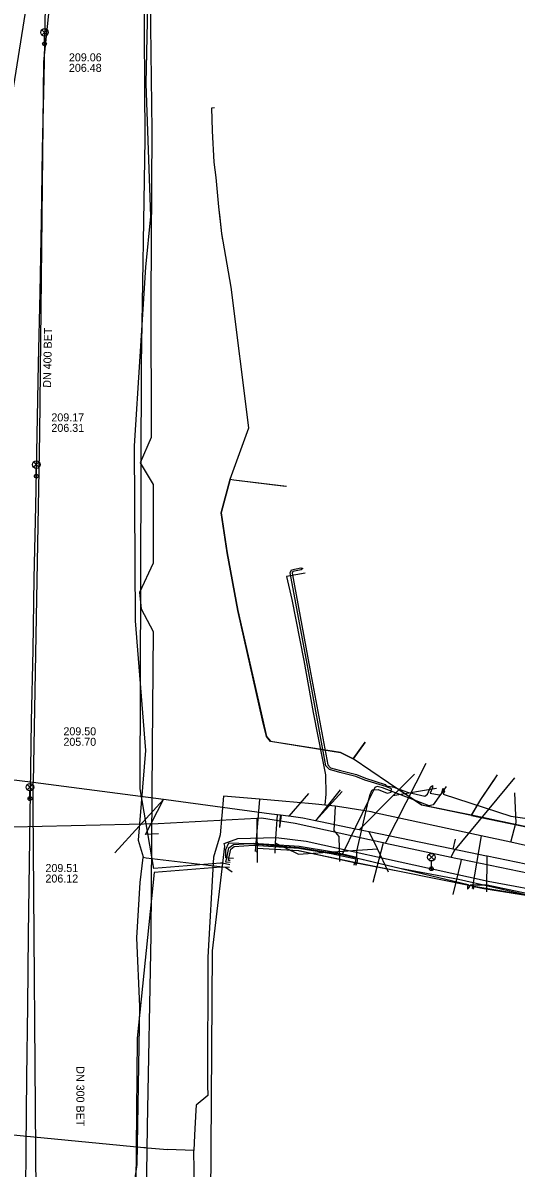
# Model space of a CAD drawing. Extents: x -596228 to -595156, y -1161235 to -1159373.
# Drawn here: x -595381.6 to -595332.3, y -1160918.3 to -1160803.8 of the extents above; entities that cross this region are included whole.
import ezdxf

# ---------------------------------------------------------------- set-up
doc = ezdxf.new("R2010")
doc.units = 0
for name, color, linetype in [('Vrstva 1', 7, 'Continuous'), ('Vrstva 12', 7, 'Continuous'), ('Vrstva 14', 7, 'Continuous'), ('Vrstva 19', 7, 'Continuous'), ('Vrstva 33', 7, 'Continuous'), ('Vrstva 4', 7, 'Continuous'), ('Vrstva 42', 7, 'Continuous'), ('Vrstva 55', 7, 'Continuous'), ('Vrstva 58', 7, 'Continuous'), ('Vrstva 9', 7, 'Continuous')]:
    doc.layers.add(name, color=color, linetype=linetype)

msp = doc.modelspace()

# ---------------------------------------------------------------- linework, layer by layer
at = {"layer": 'Vrstva 1'}
for p, q in [((-595376.97, -1160781.85), (-595379.56, -1160807.66)), ((-595379.56, -1160807.66), (-595379.97, -1160844.82)), ((-595379.97, -1160844.82), (-595380.588, -1160879.723)), ((-595353.088, -1160880.83), (-595355.059, -1160883.092)), ((-595349.92, -1160880.45), (-595352.386, -1160883.54)), ((-595349.7, -1160880.63), (-595352.386, -1160883.54)), ((-595340.28, -1160880.31), (-595344.648, -1160881.05)), ((-595380.27, -1160925.02), (-595380.587, -1160882.118)), ((-595372.43, -1160886.757), (-595367.588, -1160881.426)), ((-595355.95, -1160884.2), (-595355.871, -1160882.985)), ((-595355.95, -1160884.2), (-595355.791, -1160882.996)), ((-595354.1, -1160886.87), (-595356.37, -1160885.77)), ((-595354.1, -1160886.87), (-595346.196, -1160886.34)), ((-595335.25, -1160890.65), (-595335.209, -1160887.095))]:
    msp.add_line(p, q, dxfattribs=at)
msp.add_lwpolyline([(-595368.06, -1160884.86), (-595369.38, -1160884.9), (-595367.588, -1160881.426)], dxfattribs=at)
at = {"layer": 'Vrstva 12'}
for p, q in [((-595347.4, -1160875.67), (-595348.63, -1160877.36)), ((-595334.83, -1160879.89), (-595334.2, -1160878.96)), ((-595348.48, -1160887.73), (-595353.95, -1160886.57)), ((-595348.48, -1160887.73), (-595348.55, -1160887.98)), ((-595336.56, -1160890.1), (-595336.62, -1160890.37))]:
    msp.add_line(p, q, dxfattribs=at)
for points in [[(-595360.07, -1160776.1), (-595360.7, -1160776.59), (-595366.01, -1160779.21), (-595368.58, -1160780.95), (-595368.76, -1160783.5), (-595369.34, -1160809.83), (-595368.87, -1160823.11), (-595369.36, -1160828.18), (-595370.51, -1160846.06), (-595370.42, -1160863.54), (-595369.37, -1160876.51), (-595370.12, -1160885.48)], [(-595360.9, -1160849.38), (-595359.05, -1160844.26), (-595360.81, -1160830.19), (-595361.75, -1160824.84), (-595361.92, -1160823.26), (-595362.04, -1160822.15), (-595362.3, -1160819.23), (-595362.51, -1160817.69), (-595362.67, -1160814.56), (-595362.75, -1160812.26), (-595362.47, -1160812.23)], [(-595360.9, -1160849.38), (-595361.82, -1160852.74), (-595361.21, -1160856.74), (-595360.13, -1160862.53), (-595357.66, -1160873.49), (-595357.27, -1160875.13), (-595356.89, -1160875.6), (-595349.89, -1160876.71), (-595348.63, -1160877.36)], [(-595360.9, -1160849.38), (-595360.55, -1160849.47), (-595355.39, -1160850.09)], [(-595336.79, -1160883), (-595341.77, -1160881.99), (-595345.08, -1160879.74), (-595348.63, -1160877.36)], [(-595336.79, -1160883), (-595335.84, -1160881.4), (-595334.83, -1160879.89)], [(-595336.79, -1160883), (-595331.17, -1160884.18), (-595325.4, -1160885.36)], [(-595370.12, -1160885.48), (-595369.61, -1160887.15), (-595369.62, -1160887.23)], [(-595353.95, -1160886.57), (-595354.04, -1160886.55), (-595358.2, -1160886.33), (-595358.27, -1160886.69)], [(-595371, -1160930.92), (-595371.16, -1160924.56), (-595370.19, -1160917.92), (-595369.95, -1160902.1), (-595370.25, -1160895.24), (-595369.91, -1160889.72), (-595369.62, -1160887.23)], [(-595360.72, -1160888.68), (-595361.37, -1160888.2), (-595369.32, -1160887.27), (-595369.62, -1160887.23)], [(-595336.56, -1160890.1), (-595344, -1160888.63), (-595348.48, -1160887.73)], [(-595336.56, -1160890.1), (-595335.55, -1160890.3), (-595328.43, -1160891.46), (-595327.74, -1160891.62)]]:
    msp.add_lwpolyline(points, dxfattribs=at)
at = {"layer": 'Vrstva 14'}
msp.add_line((-595344.28, -1160886.02), (-595344.274, -1160886.003), dxfattribs=at)
for points in [[(-595393.342, -1160876.76), (-595392.99, -1160875.24), (-595390.499, -1160859.689), (-595390.026, -1160856.737), (-595387.754, -1160842.558), (-595386.046, -1160831.895), (-595382.445, -1160809.421), (-595378.386, -1160784.054), (-595376.306, -1160771.081), (-595374.576, -1160760.301), (-595372.949, -1160750.146)], [(-595345.386, -1160885.774), (-595345.308, -1160885.655), (-595341.314, -1160877.783)], [(-595338.83, -1160887.18), (-595338.802, -1160887.129), (-595338.54, -1160886.628), (-595332.459, -1160879.253)], [(-595391.32, -1160884.36), (-595368.12, -1160883.82), (-595358.229, -1160883.274), (-595357.79, -1160883.25), (-595354.4, -1160883.77), (-595345.612, -1160885.724), (-595345.386, -1160885.774), (-595344.28, -1160886.02), (-595338.83, -1160887.18), (-595338.36, -1160887.28), (-595337.816, -1160887.395), (-595326.239, -1160889.77)], [(-595358.229, -1160883.274), (-595358.236, -1160883.57), (-595358.214, -1160887.718)], [(-595345.612, -1160885.724), (-595345.643, -1160885.87), (-595346.643, -1160889.717)], [(-595337.816, -1160887.395), (-595337.864, -1160887.628), (-595338.657, -1160890.917)]]:
    msp.add_lwpolyline(points, dxfattribs=at)
at = {"layer": 'Vrstva 19'}
for p, q in [((-595357.97, -1160881.37), (-595358.42, -1160886.62)), ((-595332.48, -1160880.76), (-595332.36, -1160883.77)), ((-595332.84, -1160885.69), (-595332.36, -1160883.77)), ((-595335.82, -1160885.05), (-595336.73, -1160890.31))]:
    msp.add_line(p, q, dxfattribs=at)
for points in [[(-595353.41, -1160858.8), (-595355.28, -1160859.11), (-595354.76, -1160861.42), (-595353.55, -1160867.51), (-595352.62, -1160872.73), (-595351.72, -1160877.3), (-595351.37, -1160878.95), (-595351.35, -1160880.88), (-595351.45, -1160881.96), (-595351.451, -1160881.969)], [(-595321.44, -1160888.27), (-595332.84, -1160885.69), (-595335.82, -1160885.05), (-595346.31, -1160882.77), (-595346.82, -1160882.66), (-595349.76, -1160882.17), (-595350.43, -1160882.07), (-595351.451, -1160881.969), (-595352.04, -1160881.91), (-595352.71, -1160881.85), (-595355.7, -1160881.57), (-595357.97, -1160881.37), (-595361.58, -1160881.08), (-595361.92, -1160884.95), (-595362.58, -1160887.19), (-595363.14, -1160897.18), (-595363.18, -1160909.99), (-595363.13, -1160911.02), (-595364.31, -1160911.98), (-595364.33, -1160912.48), (-595364.46, -1160914.98), (-595364.54, -1160916.5)], [(-595350.43, -1160882.07), (-595350.55, -1160884.53), (-595350.04, -1160885.13), (-595349.98, -1160887.63)], [(-595394.61, -1160913.84), (-595393.96, -1160913.86), (-595369.538, -1160916.205), (-595369.367, -1160916.221), (-595369.16, -1160916.24), (-595367.18, -1160916.4)], [(-595364.47, -1160922.43), (-595364.47, -1160922.01), (-595364.49, -1160920.51), (-595364.54, -1160916.5), (-595367.18, -1160916.4)]]:
    msp.add_lwpolyline(points, dxfattribs=at)
at = {"layer": 'Vrstva 33'}
for p, q in [((-595379.73, -1160804.452), (-595379.2, -1160804.982)), ((-595379.73, -1160804.982), (-595379.2, -1160804.452)), ((-595379.465, -1160805.867), (-595379.465, -1160805.092)), ((-595380.555, -1160847.665), (-595380.025, -1160848.195)), ((-595380.555, -1160848.195), (-595380.025, -1160847.665)), ((-595380.29, -1160849.08), (-595380.29, -1160848.305)), ((-595381.185, -1160879.915), (-595380.655, -1160880.445)), ((-595381.185, -1160880.445), (-595380.655, -1160879.915)), ((-595380.92, -1160881.33), (-595380.92, -1160880.555)), ((-595341.061, -1160886.925), (-595340.531, -1160887.455)), ((-595341.061, -1160887.455), (-595340.531, -1160886.925)), ((-595340.796, -1160888.34), (-595340.796, -1160887.565))]:
    msp.add_line(p, q, dxfattribs=at)
for centre, radius in [((-595379.465, -1160804.717), 0.375), ((-595379.465, -1160805.867), 0.19), ((-595379.465, -1160805.867), 0.05), ((-595380.29, -1160847.93), 0.375), ((-595380.29, -1160849.08), 0.19), ((-595380.29, -1160849.08), 0.05), ((-595380.92, -1160880.18), 0.375), ((-595380.92, -1160881.33), 0.19), ((-595380.92, -1160881.33), 0.05), ((-595340.796, -1160887.19), 0.375), ((-595340.796, -1160888.34), 0.19), ((-595340.796, -1160888.34), 0.05)]:
    msp.add_circle(centre, radius, dxfattribs=at)
at = {"layer": 'Vrstva 42'}
for points in [[(-595360.942, -1160887.953), (-595361.681, -1160887.771), (-595361.89, -1160887.789), (-595368.555, -1160888.332), (-595369.891, -1160880.348), (-595369.758, -1160837.889), (-595369.417, -1160815.417), (-595369.511, -1160799.294), (-595369.472, -1160787.438), (-595369.168, -1160785.319), (-595367.921, -1160782.202), (-595365.224, -1160779.48), (-595359.713, -1160774.957), (-595353.602, -1160770.201)], [(-595368.95, -1160798.91), (-595368.74, -1160814.52), (-595368.85, -1160831.39), (-595368.79, -1160845.22), (-595369.91, -1160847.75), (-595368.62, -1160849.92), (-595368.6, -1160857.77), (-595369.97, -1160860.72), (-595369.8, -1160862.36), (-595368.62, -1160864.61), (-595368.7, -1160876.19), (-595368.84, -1160894.98), (-595369.21, -1160914.12), (-595369.46, -1160932.88), (-595369.43, -1160940.2), (-595368.85, -1160943.84), (-595367.96, -1160947.54), (-595367.92, -1160960.44), (-595367.44, -1160972.31), (-595366.8, -1160974.13), (-595366.35, -1160984.63)], [(-595346.12, -1160880.424), (-595345.22, -1160880.774), (-595344.82, -1160880.674), (-595344.807, -1160880.593), (-595344.77, -1160880.354), (-595345.359, -1160880.129), (-595347.443, -1160879.488), (-595348.362, -1160879.119), (-595349.936, -1160878.7), (-595350.973, -1160878.413), (-595351.333, -1160878.042), (-595353.128, -1160868.392), (-595354.925, -1160858.736), (-595354.764, -1160858.455), (-595353.851, -1160858.267), (-595353.63, -1160858.324), (-595353.829, -1160858.467), (-595354.636, -1160858.633), (-595354.715, -1160858.772), (-595352.932, -1160868.355), (-595351.147, -1160877.946), (-595350.867, -1160878.235), (-595349.884, -1160878.507), (-595348.298, -1160878.929), (-595347.377, -1160879.299), (-595345.426, -1160879.9), (-595345.33, -1160880.034)], [(-595339.31, -1160880.103), (-595339.564, -1160880.458), (-595339.764, -1160880.74), (-595339.884, -1160880.907), (-595340.63, -1160881.952), (-595341.007, -1160882.065), (-595344.807, -1160880.593), (-595345.683, -1160880.254), (-595346.211, -1160880.103), (-595346.437, -1160880.216), (-595346.553, -1160880.454), (-595347.078, -1160881.532), (-595349.669, -1160886.856), (-595349.7, -1160886.919)], [(-595345.33, -1160880.034), (-595344.73, -1160880.164), (-595344.665, -1160880.16), (-595343.17, -1160880.68), (-595341.44, -1160881.07), (-595341.185, -1160880.89), (-595340.879, -1160880.167), (-595340.7, -1160880), (-595340.695, -1160880.245), (-595340.929, -1160880.797), (-595340.02, -1160880.95), (-595339.884, -1160880.907), (-595339.822, -1160880.888), (-595339.764, -1160880.74), (-595339.673, -1160880.504), (-595339.66, -1160880.31), (-595339.564, -1160880.458), (-595339.487, -1160880.576), (-595339.605, -1160880.881), (-595332.84, -1160883.09), (-595331.46, -1160883.28), (-595330.61, -1160883.19), (-595330.25, -1160882.51)], [(-595360.915, -1160887.719), (-595361.332, -1160887.693), (-595361.239, -1160887.248), (-595361.03, -1160886.253), (-595360.587, -1160885.912), (-595359.01, -1160885.817), (-595358.57, -1160885.79), (-595354.009, -1160886.091), (-595350.781, -1160886.612), (-595349.669, -1160886.856), (-595348.252, -1160887.167), (-595348.26, -1160886.59), (-595347.078, -1160881.532), (-595346.93, -1160880.9), (-595346.7, -1160880.464), (-595346.553, -1160880.454), (-595346.12, -1160880.424)], [(-595360.591, -1160887.312), (-595361.038, -1160887.268), (-595361.239, -1160887.248), (-595361.329, -1160887.239), (-595361.348, -1160886.418), (-595361.038, -1160885.752), (-595359.01, -1160885.817), (-595358.495, -1160885.833), (-595354.007, -1160886.225), (-595349.7, -1160886.919), (-595343.935, -1160888.285), (-595338.102, -1160889.367), (-595335.587, -1160889.94), (-595331.083, -1160890.966)], [(-595360.903, -1160887.519), (-595361.088, -1160887.507), (-595361.038, -1160887.268), (-595360.85, -1160886.367), (-595360.513, -1160886.108), (-595358.57, -1160885.99), (-595354.031, -1160886.289), (-595350.819, -1160886.808), (-595348.363, -1160887.348), (-595348.422, -1160887.732), (-595348.36, -1160887.989), (-595348.224, -1160887.762), (-595348.152, -1160887.293), (-595337.118, -1160889.917), (-595337.203, -1160890.136), (-595337.19, -1160890.38), (-595337.017, -1160890.208), (-595336.913, -1160889.94), (-595335.587, -1160889.94), (-595335.22, -1160889.94), (-595324.06, -1160892.33)], [(-595360.976, -1160888.219), (-595361.748, -1160888.179), (-595361.844, -1160888.189), (-595368.497, -1160888.71), (-595370.195, -1160905.271), (-595370.327, -1160919.944), (-595370.786, -1160923.222), (-595369.629, -1160942.031), (-595368.904, -1160948.154), (-595369, -1160955.571), (-595369.135, -1160956.208), (-595368.895, -1160956.92)]]:
    msp.add_lwpolyline(points, dxfattribs=at)
at = {"layer": 'Vrstva 55'}
for points in [[(-595379.39, -1160802.14), (-595379.54, -1160809.29), (-595379.69, -1160816.42), (-595379.81, -1160823.57), (-595379.95, -1160830.73), (-595380.1, -1160837.86), (-595380.22, -1160844.96), (-595380.37, -1160852.09), (-595380.52, -1160859.32), (-595380.64, -1160866.45), (-595380.79, -1160873.58), (-595381.01, -1160887.74), (-595381.11, -1160894.92), (-595381.18, -1160902.05), (-595381.28, -1160909.18), (-595381.35, -1160916.31), (-595381.38, -1160920.58), (-595381.079, -1160921.749), (-595381.01, -1160930.52), (-595380.71, -1160937.78), (-595379.526, -1160956.433), (-595379.423, -1160959.056), (-595377.97, -1160988.68)], [(-595368.38, -1160960.57), (-595366.535, -1160960.59), (-595367.1, -1160959.08), (-595366.79, -1160953.56), (-595359.87, -1160953.93), (-595359.3, -1160943.45), (-595362.11, -1160937.46), (-595362.843, -1160921.325), (-595362.687, -1160896.538), (-595361.44, -1160886.092), (-595361.51, -1160885.81)], [(-595361.51, -1160885.81), (-595360.14, -1160885.32), (-595356.31, -1160885.23), (-595353.31, -1160885.59), (-595340.87, -1160888.316), (-595340.79, -1160888.36), (-595340.713, -1160888.35), (-595335.11, -1160889.59), (-595328.28, -1160890.85)]]:
    msp.add_lwpolyline(points, dxfattribs=at)
at = {"layer": 'Vrstva 58'}
for p, q in [((-595362.513, -1160817.692), (-595362.67, -1160814.564)), ((-595362.3, -1160819.234), (-595362.513, -1160817.692)), ((-595362.036, -1160822.152), (-595362.3, -1160819.234)), ((-595360.897, -1160849.377), (-595360.545, -1160849.47)), ((-595360.545, -1160849.47), (-595355.268, -1160850.101)), ((-595349.892, -1160876.711), (-595356.891, -1160875.602)), ((-595348.628, -1160877.363), (-595347.402, -1160875.681)), ((-595348.477, -1160887.733), (-595348.542, -1160887.978)), ((-595336.56, -1160890.1), (-595336.622, -1160890.375)), ((-595328.425, -1160891.463), (-595335.545, -1160890.296))]:
    msp.add_line(p, q, dxfattribs=at)
for points in [[(-595362.67, -1160814.564), (-595362.749, -1160812.263), (-595362.466, -1160812.226)], [(-595361.637, -1160825.504), (-595361.754, -1160824.838), (-595362.036, -1160822.152)], [(-595356.891, -1160875.602), (-595357.272, -1160875.132), (-595357.662, -1160873.487), (-595360.133, -1160862.526), (-595361.209, -1160856.741), (-595361.818, -1160852.741), (-595360.897, -1160849.377), (-595359.05, -1160844.263), (-595360.815, -1160830.19), (-595361.754, -1160824.838), (-595361.919, -1160823.265)], [(-595341.768, -1160881.988), (-595345.079, -1160879.743), (-595348.628, -1160877.363), (-595349.892, -1160876.711)], [(-595336.789, -1160882.998), (-595335.844, -1160881.4), (-595334.438, -1160879.302)], [(-595331.167, -1160884.182), (-595336.789, -1160882.998), (-595341.768, -1160881.988)], [(-595335.545, -1160890.296), (-595336.56, -1160890.1), (-595344.001, -1160888.629), (-595348.477, -1160887.733), (-595354.037, -1160886.551), (-595358.198, -1160886.329), (-595358.269, -1160886.679)]]:
    msp.add_lwpolyline(points, dxfattribs=at)
at = {"layer": 'Vrstva 9'}
for p, q in [((-595380.588, -1160879.723), (-595394.967, -1160878.021)), ((-595380.587, -1160882.118), (-595380.588, -1160879.723)), ((-595338.434, -1160885.399), (-595338.637, -1160886.378))]:
    msp.add_line(p, q, dxfattribs=at)
for points in [[(-595342.492, -1160878.872), (-595344.648, -1160881.05), (-595348.009, -1160884.447)], [(-595353.64, -1160883.28), (-595355.059, -1160883.092), (-595355.127, -1160883.083), (-595355.871, -1160882.985), (-595356.19, -1160882.943), (-595356.763, -1160882.867), (-595367.3, -1160881.464), (-595367.588, -1160881.426), (-595380.588, -1160879.723)], [(-595356.428, -1160886.768), (-595356.37, -1160885.77), (-595356.19, -1160882.943)], [(-595310.64, -1160892.18), (-595311.485, -1160892.005), (-595312.492, -1160891.797), (-595313.442, -1160891.6), (-595313.802, -1160891.526), (-595321.687, -1160889.893), (-595322.047, -1160889.819), (-595327.34, -1160888.722), (-595327.504, -1160888.688), (-595335.209, -1160887.095), (-595335.279, -1160887.08), (-595338.637, -1160886.378), (-595338.803, -1160886.344), (-595347.001, -1160884.656), (-595347.393, -1160884.575), (-595348.009, -1160884.447), (-595348.392, -1160884.368), (-595351.877, -1160883.645), (-595352.386, -1160883.54), (-595353.64, -1160883.28)], [(-595345.085, -1160888.666), (-595346.196, -1160886.34), (-595347.001, -1160884.656)]]:
    msp.add_lwpolyline(points, dxfattribs=at)

# ---------------------------------------------------------------- texts
at = {"layer": 'Vrstva 12'}
for s, p in [('209.50', (-595377.576, -1160874.998)), ('205.70', (-595377.576, -1160876.048)), ('209.51', (-595379.373, -1160888.67)), ('206.12', (-595379.373, -1160889.72))]:
    msp.add_text(s, height=0.8, dxfattribs=at).set_placement(p)
at = {"layer": 'Vrstva 4'}
for s, p in [('209.06', (-595377.026, -1160807.61)), ('206.48', (-595377.026, -1160808.66)), ('209.17', (-595378.779, -1160843.609)), ('206.31', (-595378.779, -1160844.659))]:
    msp.add_text(s, height=0.8, dxfattribs=at).set_placement(p)
for s, rotation, p in [('DN 400 BET', 89, (-595378.818, -1160840.249)), ('DN 300 BET', 270, (-595376.28, -1160908.089))]:
    msp.add_text(s, height=0.8, rotation=rotation, dxfattribs=at).set_placement(p)

doc.saveas('drawing.dxf')
